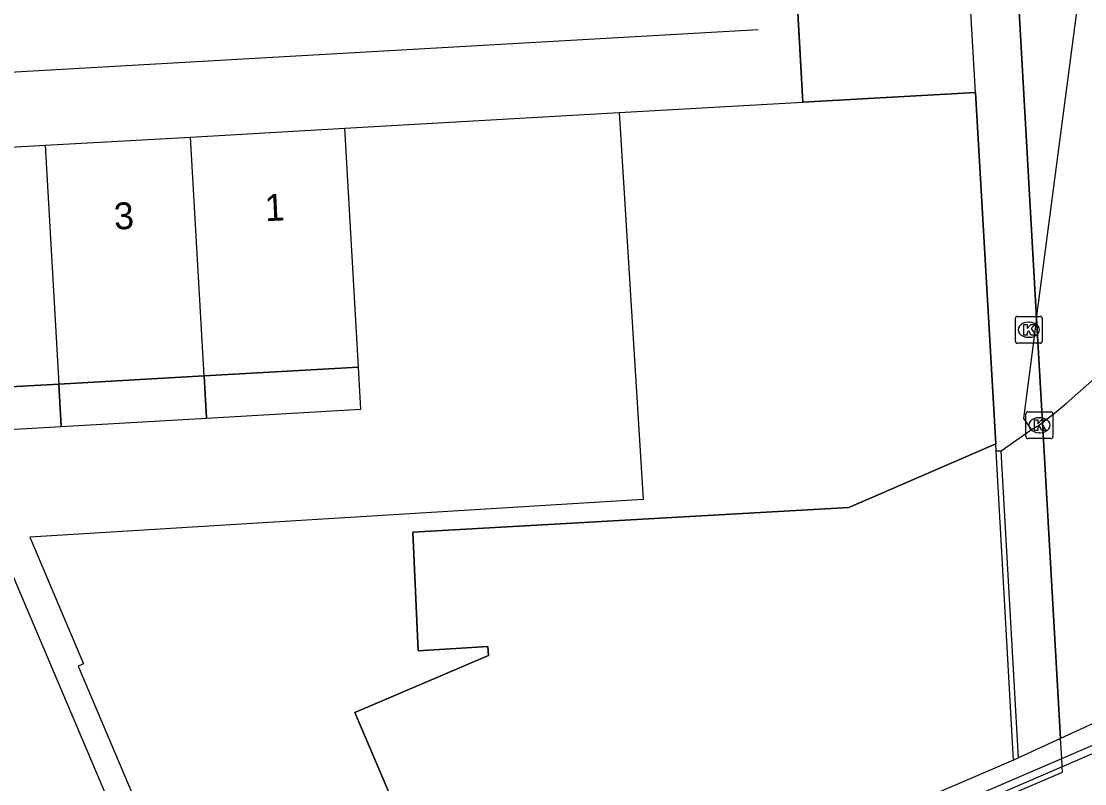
# Model space of a CAD drawing. Extents: x 155640 to 156810, y 382822 to 384046.
# Drawn here: x 156597.01 to 156636.67, y 383789.39 to 383817.83 of the extents above; entities that cross this region are included whole.
import ezdxf

# ---------------------------------------------------------------- set-up
doc = ezdxf.new("R2010")
doc.units = 0
for name, color, linetype in [('IMGEO_Groenvoorziening', 7, 'Continuous'), ('IMGEO_Kolk', 7, 'Continuous'), ('IMGEO_Lijnafwatering', 7, 'Continuous'), ('IMGEO_Muur', 7, 'Continuous'), ('IMGEO_Pand', 7, 'Continuous'), ('IMGEO_Pand_nummerreeks', 7, 'Continuous'), ('IMGEO_Pand_overbouw', 7, 'Continuous'), ('IMGEO_Rijbaan_lokaal_gesloten', 7, 'Continuous'), ('IMGEO_Verkeerseiland_open', 7, 'Continuous'), ('IMGEO_Voetgangersgebied_open', 7, 'Continuous'), ('IMGEO_Voetpad_op_trap', 7, 'Continuous'), ('IMGEO_Voetpad_open', 7, 'Continuous')]:
    doc.layers.add(name, color=color, linetype=linetype)

msp = doc.modelspace()

# ---------------------------------------------------------------- linework, layer by layer
at = {"layer": 'IMGEO_Groenvoorziening'}
msp.add_lwpolyline([(156634.878, 383806.75), (156635.1, 383802.859)], dxfattribs=at)
at = {"layer": 'IMGEO_Kolk'}
for p, q in [((156634.085, 383805.896), (156634.085, 383806.748)), ((156634.16, 383806.822), (156635.012, 383806.822)), ((156634.573, 383806.602), (156634.598, 383806.602)), ((156635.086, 383806.748), (156635.086, 383805.896)), ((156635.012, 383805.822), (156634.16, 383805.822)), ((156634.596, 383806.042), (156634.571, 383806.042)), ((156634.481, 383802.339), (156634.481, 383803.191)), ((156634.556, 383803.265), (156635.408, 383803.265)), ((156634.969, 383803.045), (156634.994, 383803.045)), ((156635.482, 383803.191), (156635.482, 383802.339)), ((156635.408, 383802.265), (156634.556, 383802.265)), ((156634.992, 383802.485), (156634.967, 383802.485))]:
    msp.add_line(p, q, dxfattribs=at)
for points in [[(156634.085, 383805.896), (156634.085, 383806.748)], [(156634.16, 383806.822), (156635.012, 383806.822)], [(156635.086, 383806.748), (156635.086, 383805.896)], [(156634.406, 383806.522), (156634.529, 383806.522), (156634.529, 383806.371), (156634.659, 383806.522), (156634.823, 383806.522), (156634.677, 383806.371), (156634.83, 383806.122), (156634.678, 383806.122), (156634.593, 383806.286), (156634.529, 383806.219), (156634.529, 383806.122), (156634.406, 383806.122), (156634.406, 383806.522)], [(156635.012, 383805.822), (156634.16, 383805.822)], [(156634.481, 383802.339), (156634.481, 383803.191)], [(156634.556, 383803.265), (156635.408, 383803.265)], [(156635.482, 383803.191), (156635.482, 383802.339)], [(156634.802, 383802.965), (156634.925, 383802.965), (156634.925, 383802.814), (156635.055, 383802.965), (156635.219, 383802.965), (156635.073, 383802.814), (156635.226, 383802.565), (156635.074, 383802.565), (156634.989, 383802.729), (156634.925, 383802.662), (156634.925, 383802.565), (156634.802, 383802.565), (156634.802, 383802.965)], [(156635.408, 383802.265), (156634.556, 383802.265)]]:
    msp.add_lwpolyline(points, dxfattribs=at)
for centre, start, end in [((156634.162, 383806.746), 91.552, 178.448), ((156634.162, 383806.746), 91.552, 178.448), ((156635.01, 383806.746), 1.552, 88.448), ((156635.01, 383806.746), 1.552, 88.448), ((156634.162, 383805.898), 181.552, 268.448), ((156634.162, 383805.898), 181.552, 268.448), ((156635.01, 383805.898), 271.552, 358.448), ((156635.01, 383805.898), 271.552, 358.448), ((156634.558, 383803.189), 91.552, 178.448), ((156634.558, 383803.189), 91.552, 178.448), ((156635.406, 383803.189), 1.552, 88.448), ((156635.406, 383803.189), 1.552, 88.448), ((156634.558, 383802.341), 181.552, 268.448), ((156634.558, 383802.341), 181.552, 268.448), ((156635.406, 383802.341), 271.552, 358.448), ((156635.406, 383802.341), 271.552, 358.448)]:
    msp.add_arc(centre, 0.0765, start, end, dxfattribs=at)
for centre, major_axis, ratio, start_param, end_param in [((156634.572, 383806.322), (-0.387, 0.002), 0.722429, 4.712389, 7.853982), ((156634.597, 383806.322), (-0.39, 0.002), 0.717154, 1.570796, 4.712389), ((156634.968, 383802.765), (-0.387, 0.002), 0.722429, 4.712389, 7.853982), ((156634.993, 383802.765), (-0.39, 0.002), 0.717154, 1.570796, 4.712389)]:
    msp.add_ellipse(centre, major_axis=major_axis, ratio=ratio, start_param=start_param, end_param=end_param, dxfattribs=at)
at = {"layer": 'IMGEO_Lijnafwatering'}
for points in [[(156624.489, 383817.505), (156599.18, 383816.064)], [(156599.18, 383816.064), (156573.301, 383814.59)], [(156634.202, 383790.354), (156633.561, 383801.797)]]:
    msp.add_lwpolyline(points, dxfattribs=at)
at = {"layer": 'IMGEO_Muur'}
for points in [[(156609.074, 383813.84), (156619.306, 383814.422)], [(156646.714, 383795.019), (156646.536, 383794.644), (156635.833, 383790.028), (156614.281, 383780.732)], [(156635.815, 383790.33), (156646.714, 383795.019)], [(156614.16, 383781.013), (156635.815, 383790.33)]]:
    msp.add_lwpolyline(points, dxfattribs=at)
at = {"layer": 'IMGEO_Pand'}
for points in [[(156632.602, 383815.173), (156626.163, 383814.812)], [(156633.356, 383802.068), (156632.602, 383815.173)], [(156619.306, 383814.422), (156626.163, 383814.812)], [(156619.306, 383814.422), (156620.197, 383799.996), (156597.327, 383798.583), (156599.334, 383793.861), (156599.125, 383793.772), (156601.176, 383788.945), (156600.332, 383788.586), (156594.507, 383802.295), (156565.638, 383800.613), (156545.7, 383792.039), (156538.063, 383809.8)], [(156603.317, 383813.512), (156609.074, 383813.84)], [(156609.581, 383804.935), (156609.074, 383813.84)], [(156597.896, 383813.204), (156603.317, 383813.512)], [(156603.824, 383804.608), (156603.317, 383813.512)], [(156592.458, 383812.894), (156597.896, 383813.204)], [(156597.896, 383813.204), (156598.403, 383804.3)], [(156603.824, 383804.608), (156609.581, 383804.935)], [(156592.965, 383803.991), (156598.403, 383804.3)], [(156598.403, 383804.3), (156603.824, 383804.608)], [(156613.727, 383782.021), (156612.621, 383784.596), (156612.184, 383785.615), (156611.742, 383786.644), (156611.022, 383788.344), (156609.452, 383792.052), (156614.43, 383794.177), (156614.405, 383794.505), (156611.806, 383794.349), (156611.616, 383798.773), (156627.87, 383799.699), (156633.356, 383802.068)]]:
    msp.add_lwpolyline(points, dxfattribs=at)
at = {"layer": 'IMGEO_Pand_overbouw'}
for points in [[(156614.339, 383780.597), (156635.844, 383789.823), (156635.833, 383790.028), (156635.815, 383790.33), (156635.773, 383791.076), (156635.1, 383802.859), (156634.878, 383806.75), (156634.036, 383821.502)], [(156625.819, 383820.838), (156626.163, 383814.812), (156632.602, 383815.173), (156633.356, 383802.068), (156627.87, 383799.699), (156611.616, 383798.773), (156611.806, 383794.349), (156614.405, 383794.505), (156614.43, 383794.177), (156609.452, 383792.052), (156611.022, 383788.344)]]:
    msp.add_lwpolyline(points, dxfattribs=at)
for points in [[(156603.824, 383804.608), (156603.914, 383803.029), (156609.671, 383803.357), (156609.581, 383804.935)], [(156592.965, 383803.991), (156593.055, 383802.41), (156598.493, 383802.72), (156598.403, 383804.3)], [(156603.824, 383804.608), (156598.403, 383804.3), (156598.493, 383802.72), (156603.914, 383803.029)]]:
    msp.add_lwpolyline(points, close=True, dxfattribs=at)
at = {"layer": 'IMGEO_Rijbaan_lokaal_gesloten'}
for points in [[(156635.1, 383802.859), (156635.041, 383802.812), (156634.982, 383802.765), (156634.686, 383802.586)], [(156635.1, 383802.859), (156635.773, 383791.076)], [(156634.686, 383802.586), (156633.561, 383801.797), (156633.371, 383801.793)], [(156633.371, 383801.793), (156633.356, 383802.068)], [(156634.015, 383790.269), (156633.371, 383801.793)], [(156641.123, 383793.77), (156640.265, 383793.228), (156638.482, 383792.321), (156635.773, 383791.076)], [(156635.773, 383791.076), (156634.202, 383790.354)], [(156634.202, 383790.354), (156634.015, 383790.269)], [(156634.015, 383790.269), (156616.522, 383782.757)]]:
    msp.add_lwpolyline(points, dxfattribs=at)
msp.add_arc((156612.839, 383831.056), 35.925, 308.2908, 322.7069, dxfattribs=at)
at = {"layer": 'IMGEO_Verkeerseiland_open'}
msp.add_lwpolyline([(156635.815, 383790.33), (156635.773, 383791.076)], dxfattribs=at)
at = {"layer": 'IMGEO_Voetgangersgebied_open'}
msp.add_lwpolyline([(156634.878, 383806.75), (156637.012, 383823.006)], dxfattribs=at)
at = {"layer": 'IMGEO_Voetpad_op_trap'}
msp.add_lwpolyline([(156626.163, 383814.812), (156625.808, 383821.029)], dxfattribs=at)
at = {"layer": 'IMGEO_Voetpad_open'}
for points in [[(156632.602, 383815.173), (156632.255, 383821.188), (156632.243, 383821.397)], [(156634.036, 383821.502), (156634.878, 383806.75)], [(156609.074, 383813.84), (156619.306, 383814.422)], [(156634.878, 383806.75), (156634.387, 383803.009), (156634.686, 383802.586)], [(156549.495, 383801.524), (156549.585, 383799.935), (156555.257, 383800.258), (156560.667, 383800.566), (156566.062, 383800.873), (156571.464, 383801.181), (156576.869, 383801.489), (156582.283, 383801.797), (156587.665, 383802.103), (156593.055, 383802.41), (156598.493, 383802.72), (156603.914, 383803.029), (156609.671, 383803.357), (156609.581, 383804.935)]]:
    msp.add_lwpolyline(points, dxfattribs=at)

# ---------------------------------------------------------------- texts
at = {"layer": 'IMGEO_Pand_nummerreeks'}
for s, rotation, p in [('1', 2.7274, (156606.111, 383810.37)), ('3', 3.0952, (156600.49, 383810.055))]:
    msp.add_text(s, height=1, rotation=rotation, dxfattribs=at).set_placement(p)

doc.saveas('drawing.dxf')
